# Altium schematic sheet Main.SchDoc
size A3; SheetNumber: 1; SheetTotal: 17
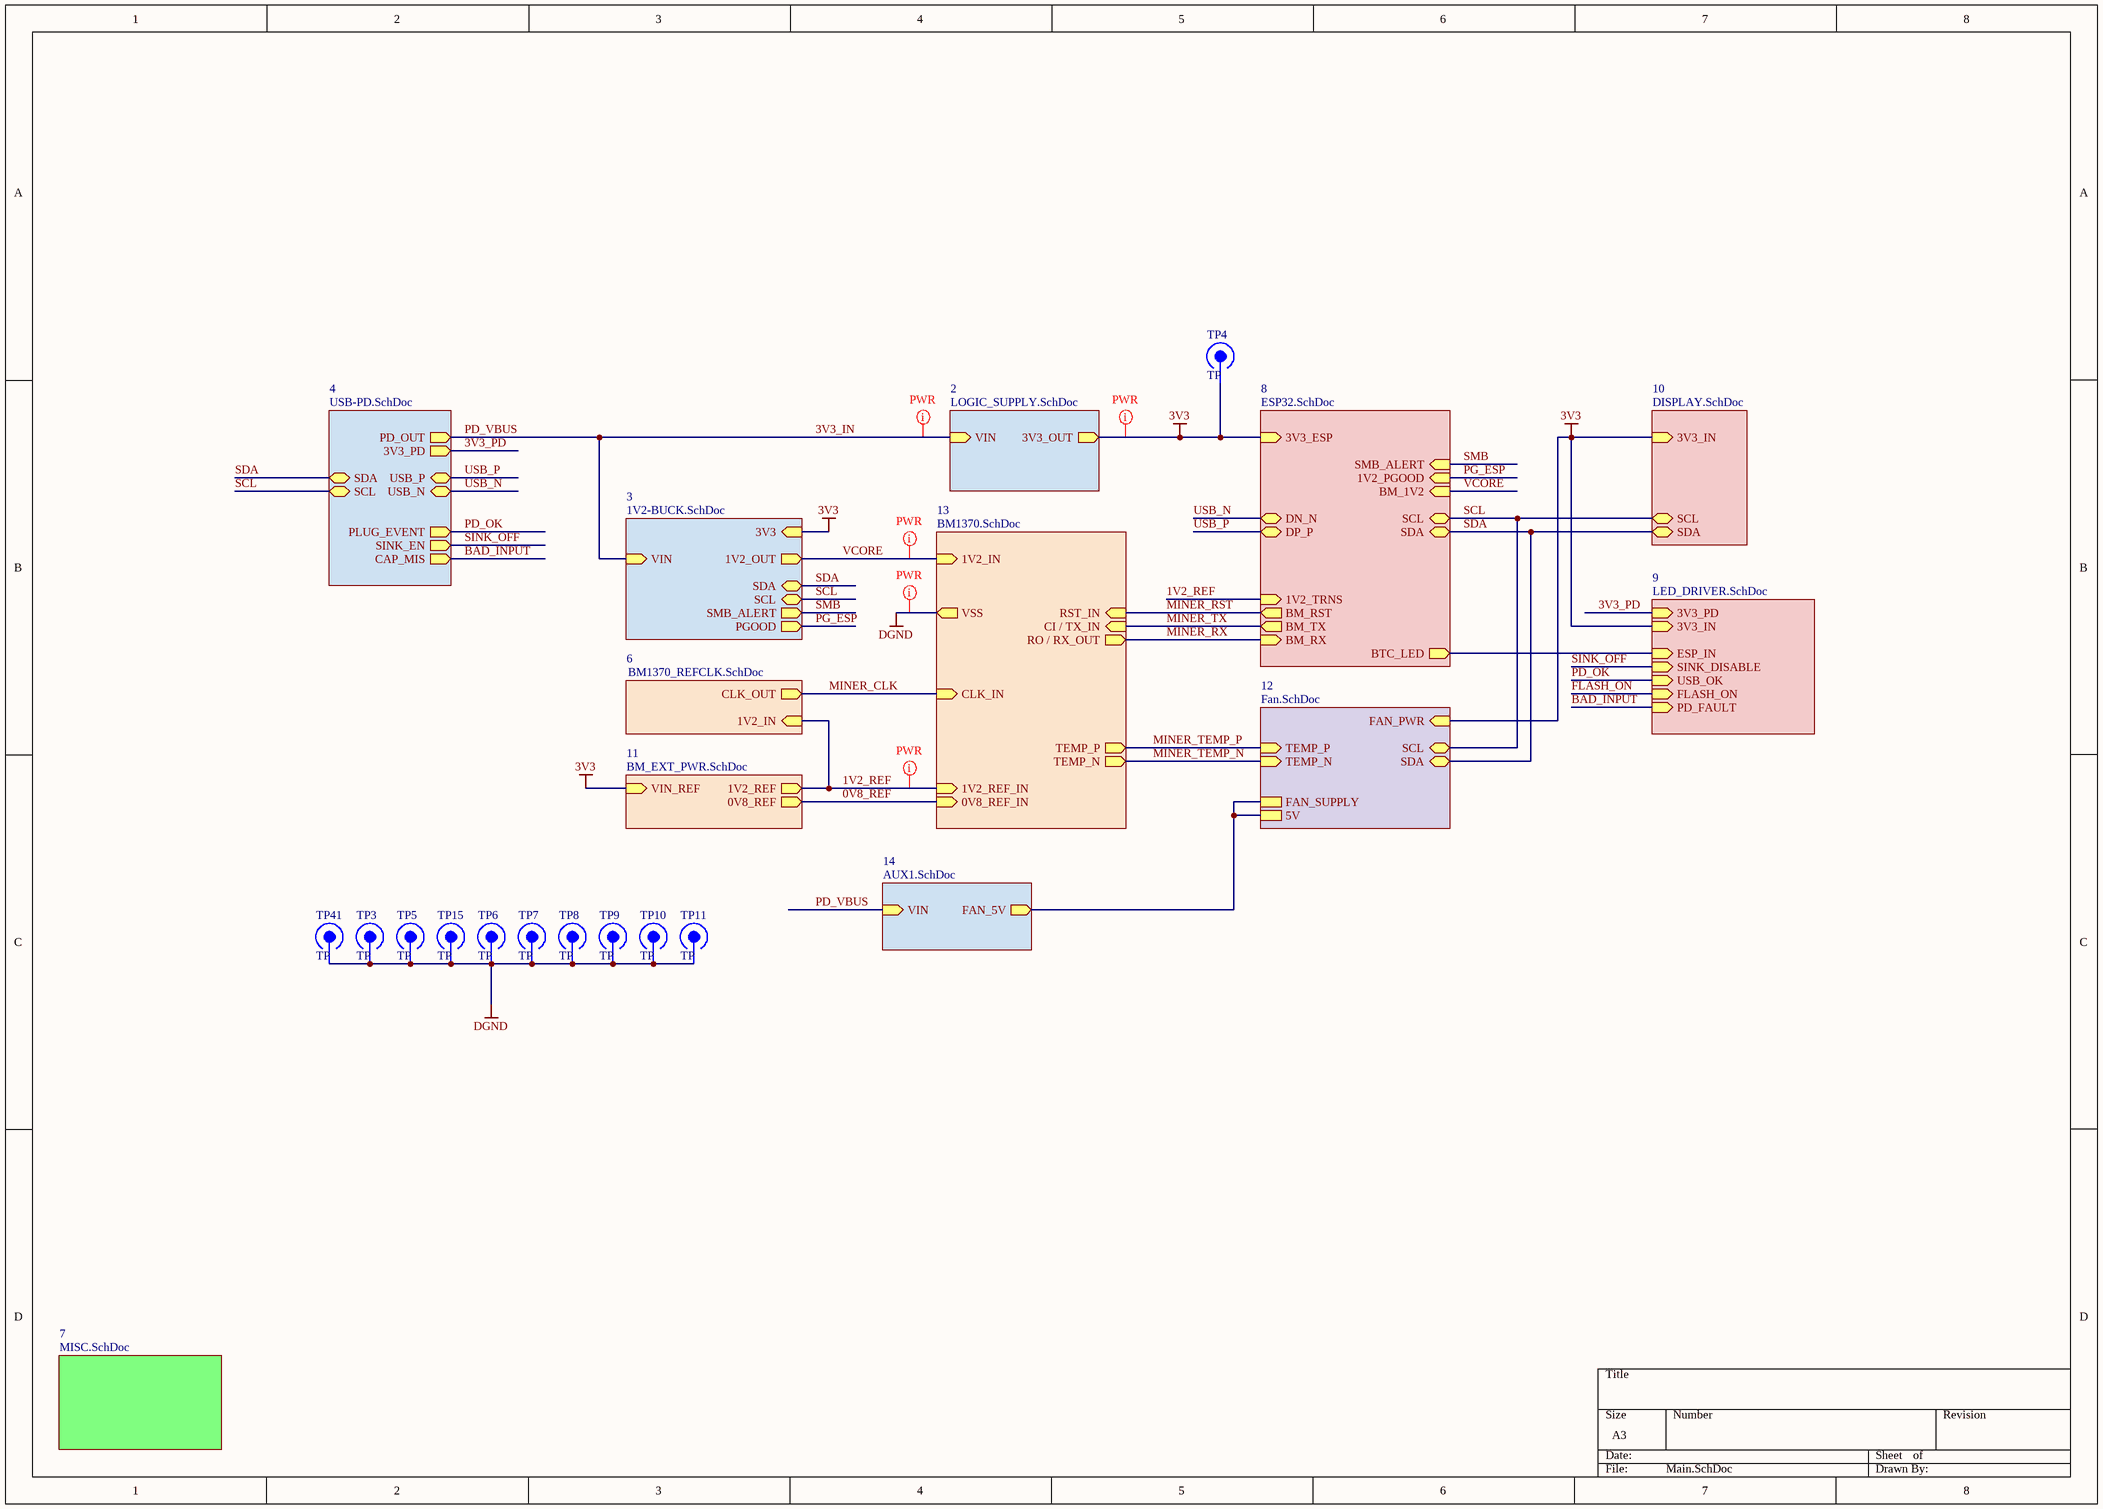
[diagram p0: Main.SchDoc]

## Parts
TP3  TP  [TP-Footprint-1]
TP4  TP  [TP-Footprint-1]
TP5  TP  [TP-Footprint-1]
TP6  TP  [TP-Footprint-1]
TP7  TP  [TP-Footprint-1]
TP8  TP  [TP-Footprint-1]
TP9  TP  [TP-Footprint-1]
TP10  TP  [TP-Footprint-1]
TP11  TP  [TP-Footprint-1]
TP15  TP  [TP-Footprint-1]
TP41  TP  [TP-Footprint-1]

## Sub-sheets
2 = LOGIC_SUPPLY.SchDoc: VIN (in), 3V3_OUT (out)
3 = 1V2-BUCK.SchDoc: VIN (in), 1V2_OUT (out), SDA (bidir), SCL (bidir), SMB_ALERT (out), 3V3 (in), PGOOD (out)
4 = USB-PD.SchDoc: PD_OUT (out), USB_P (bidir), USB_N (bidir), PLUG_EVENT (out), SINK_EN (out), CAP_MIS (out), SDA (bidir), SCL (bidir), 3V3_PD (out)
6 = BM1370_REFCLK.SchDoc: 1V2_IN (in), CLK_OUT (out)
7 = MISC.SchDoc: no entries
8 = ESP32.SchDoc: 3V3_ESP (in), DN_N (bidir), DP_P (bidir), 1V2_PGOOD (in), BM_1V2 (in), SCL (bidir), SDA (bidir), 1V2_TRNS (in), BM_RST (out), BM_TX (out), BM_RX (in), BTC_LED (out), SMB_ALERT (in)
9 = LED_DRIVER.SchDoc: 3V3_IN (in), ESP_IN (in), SINK_DISABLE (in), USB_OK (in), FLASH_ON (in), PD_FAULT (in), 3V3_PD (in)
10 = DISPLAY.SchDoc: 3V3_IN (in), SCL (bidir), SDA (bidir)
11 = BM_EXT_PWR.SchDoc: VIN_REF (in), 1V2_REF (out), 0V8_REF (out)
12 = Fan.SchDoc: SCL (bidir), SDA (bidir), TEMP_P (in), TEMP_N (in), FAN_PWR (in), FAN_SUPPLY, 5V
13 = BM1370.SchDoc: 1V2_REF_IN (in), 0V8_REF_IN (in), 1V2_IN (in), VSS (out), RST_IN (in), CI / TX_IN (in), RO / RX_OUT (out), TEMP_P (out), TEMP_N (out), CLK_IN (in)
14 = AUX1.SchDoc: VIN (in), FAN_5V (out)

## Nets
3V3: TP4.1 ; sheet 3/3V3, sheet 12/FAN_PWR, sheet 11/VIN_REF, sheet 8/3V3_ESP, sheet 2/3V3_OUT, sheet 10/3V3_IN, sheet 9/3V3_IN
DGND: TP3.1 TP5.1 TP6.1 TP7.1 TP8.1 TP9.1 TP10.1 TP11.1 TP15.1 TP41.1 ; sheet 13/VSS
0V8_REF: sheet 13/0V8_REF_IN, sheet 11/0V8_REF
1V2_REF: sheet 13/1V2_REF_IN, sheet 11/1V2_REF, sheet 6/1V2_IN, sheet 8/1V2_TRNS
3V3_IN: sheet 3/VIN, sheet 4/PD_OUT, sheet 2/VIN, sheet 14/VIN  [also labelled PD_VBUS]
3V3_PD: sheet 4/3V3_PD, sheet 9/3V3_PD
BAD_INPUT: sheet 4/CAP_MIS, sheet 9/PD_FAULT
MINER_CLK: sheet 13/CLK_IN, sheet 6/CLK_OUT
MINER_RST: sheet 13/RST_IN, sheet 8/BM_RST
MINER_RX: sheet 13/RO / RX_OUT, sheet 8/BM_RX
MINER_TEMP_N: sheet 13/TEMP_N, sheet 12/TEMP_N
MINER_TEMP_P: sheet 13/TEMP_P, sheet 12/TEMP_P
MINER_TX: sheet 13/CI / TX_IN, sheet 8/BM_TX
PD_OK: sheet 4/PLUG_EVENT, sheet 9/USB_OK
PG_ESP: sheet 3/PGOOD, sheet 8/1V2_PGOOD
SCL: sheet 3/SCL, sheet 12/SCL, sheet 4/SCL, sheet 8/SCL, sheet 10/SCL
SDA: sheet 3/SDA, sheet 12/SDA, sheet 4/SDA, sheet 8/SDA, sheet 10/SDA
SINK_OFF: sheet 4/SINK_EN, sheet 9/SINK_DISABLE
SMB: sheet 3/SMB_ALERT, sheet 8/SMB_ALERT
USB_N: sheet 4/USB_N, sheet 8/DN_N
USB_P: sheet 4/USB_P, sheet 8/DP_P
VCORE: sheet 3/1V2_OUT, sheet 13/1V2_IN, sheet 8/BM_1V2
(unnamed): sheet 12/FAN_SUPPLY, sheet 12/5V, sheet 14/FAN_5V
(unnamed): sheet 8/BTC_LED, sheet 9/ESP_IN  [a separate net that carries the same name]

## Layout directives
net class PWR: 1V2_REF, 3V3, 3V3_IN, DGND, VCORE

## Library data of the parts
TP3-TP11 TP15 TP41 = CMP-001-0086-4: digital shovel test point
